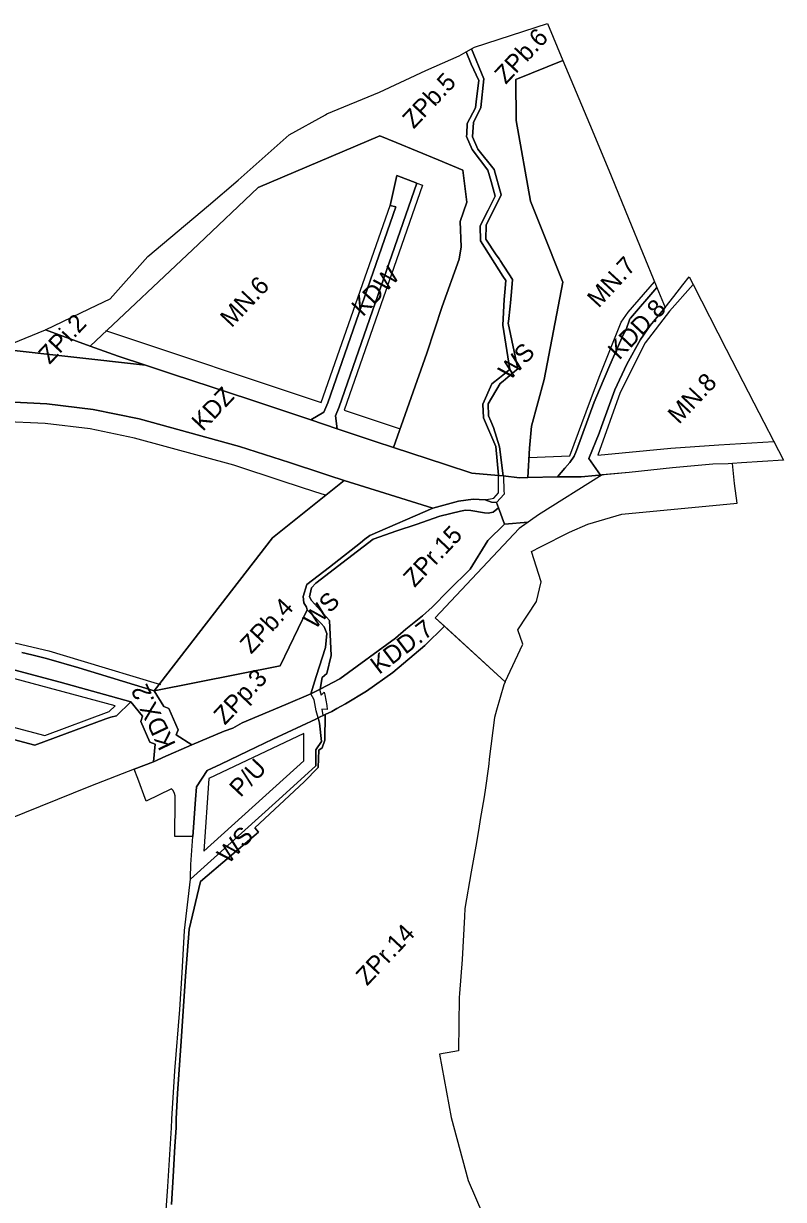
# Model space of a CAD drawing. Extents: x 7425782 to 7428854, y 5550411 to 5553074.
# Drawn here: x 7427672 to 7428056, y 5552172 to 5552767 of the extents above; entities that cross this region are included whole.
import ezdxf

# ---------------------------------------------------------------- set-up
doc = ezdxf.new("R2010")
doc.units = 0
for name, color, linetype in [('LIN_Linie rozgraniczajace WS', 7, 'Continuous'), ('LIN_linie_rozgraniczajace', 7, 'Continuous'), ('LIN_nieprzekraczalna linia zabudowy', 7, 'Continuous'), ('tereny MPZP_MISTRZEJOWICE PN', 7, 'Continuous'), ('TXT_oznaczenia przeznaczen', 7, 'Continuous')]:
    doc.layers.add(name, color=color, linetype=linetype)

msp = doc.modelspace()

# ---------------------------------------------------------------- linework, layer by layer
at = {"layer": 'LIN_Linie rozgraniczajace WS'}
for points in [[(7427906.08, 5552526.17), (7427905.67, 5552526.1), (7427910, 5552526.88), (7427912.32, 5552529.6), (7427912.33, 5552535.03), (7427912.28, 5552538.48)], [(7427914.73, 5552538.21), (7427914.82, 5552537.54), (7427915.06, 5552531.01), (7427915.15, 5552528.95), (7427911.35, 5552524.81)], [(7427821.22, 5552415.84), (7427820.92, 5552417.05), (7427820.21, 5552419.43), (7427819.29, 5552424.95), (7427817.61, 5552428.03)], [(7427822.25, 5552430.41), (7427822.12, 5552429.7), (7427822.72, 5552427.29), (7427824.33, 5552428.85), (7427824.64, 5552427.49), (7427825.55, 5552422.1), (7427825.84, 5552420.03), (7427823.16, 5552420.23), (7427823.66, 5552417)]]:
    msp.add_lwpolyline(points, dxfattribs=at)
at = {"layer": 'LIN_linie_rozgraniczajace'}
for points in [[(7427944.77, 5552748.25), (7427921.04, 5552738.69), (7427921.27, 5552717.87), (7427928.59, 5552677.19), (7427933.91, 5552663.7), (7427944.91, 5552636.14), (7427935.44, 5552586.91), (7427929.02, 5552563.42), (7427927.97, 5552552.2), (7427927.09, 5552537.4), (7427922.99, 5552537.31), (7427914.73, 5552538.21), (7427912.88, 5552552.91), (7427909.86, 5552562.77), (7427908.5, 5552565.95), (7427907.26, 5552568.62), (7427907.04, 5552574.63), (7427913.25, 5552584.87), (7427914.73, 5552586.1), (7427917.05, 5552588.08), (7427920.48, 5552590.95), (7427922.07, 5552592.29), (7427917.23, 5552615.47), (7427917.32, 5552616.25), (7427918.22, 5552624.08), (7427918.37, 5552625.68), (7427918.86, 5552631.3), (7427919.41, 5552637.52), (7427913.13, 5552647.2), (7427912.79, 5552647.73), (7427911.14, 5552649.92), (7427905.88, 5552657.85), (7427906.08, 5552664.96), (7427913.65, 5552680.24), (7427910.08, 5552693.1), (7427901.83, 5552703.44), (7427899.27, 5552709.58), (7427899.71, 5552716.95), (7427903.41, 5552724.54), (7427904.9, 5552738.91), (7427898.71, 5552754.16), (7427900.19, 5552755.02), (7427937.02, 5552766.93)], [(7427914.73, 5552538.21), (7427912.28, 5552538.48), (7427912.28, 5552538.67), (7427910.99, 5552553.07), (7427904.83, 5552567.55), (7427904.43, 5552574.52), (7427909.04, 5552584.8), (7427912.78, 5552587.81), (7427914.53, 5552589.18), (7427916.77, 5552591.01), (7427918.09, 5552592.04), (7427914.58, 5552614.34), (7427915.13, 5552627.34), (7427915.47, 5552631.16), (7427916, 5552636.95), (7427914.54, 5552639.14), (7427903.31, 5552657.05), (7427903.03, 5552664.62), (7427907.09, 5552672.58), (7427910.63, 5552679.62), (7427908.59, 5552686.98), (7427906.89, 5552692.8), (7427899.07, 5552703.21), (7427896.25, 5552709.73), (7427896.35, 5552711.13), (7427896.46, 5552716.31), (7427900.66, 5552724.29), (7427901.27, 5552728.9), (7427902.46, 5552738.14), (7427898.48, 5552746.32), (7427895.94, 5552752.56), (7427898.71, 5552754.16), (7427904.9, 5552738.91), (7427903.41, 5552724.54), (7427899.71, 5552716.95), (7427899.27, 5552709.58), (7427901.83, 5552703.44), (7427910.08, 5552693.1), (7427913.65, 5552680.24), (7427906.08, 5552664.96), (7427905.88, 5552657.85), (7427911.14, 5552649.92), (7427912.79, 5552647.73), (7427913.13, 5552647.2), (7427919.41, 5552637.52), (7427918.86, 5552631.3), (7427918.37, 5552625.68), (7427918.22, 5552624.08), (7427917.32, 5552616.25), (7427917.23, 5552615.47), (7427922.07, 5552592.29), (7427920.48, 5552590.95), (7427917.05, 5552588.08), (7427914.73, 5552586.1), (7427913.25, 5552584.87), (7427907.04, 5552574.63), (7427907.26, 5552568.62), (7427908.5, 5552565.95), (7427909.86, 5552562.77), (7427912.88, 5552552.91)], [(7427912.28, 5552538.48), (7427898.8, 5552539.53), (7427885.64, 5552543.9), (7427859.3, 5552552.58), (7427876.15, 5552600.28), (7427883.95, 5552623.89), (7427892.49, 5552647.77), (7427893.42, 5552654), (7427892.94, 5552666.85), (7427896.34, 5552676.67), (7427894.38, 5552692.8), (7427881.88, 5552697.96), (7427860.65, 5552706.7), (7427852.41, 5552710.1), (7427790.92, 5552684.04), (7427760.79, 5552655.36), (7427706.13, 5552603.86), (7427683.49, 5552612.03), (7427705.59, 5552622.65), (7427709.38, 5552624.47), (7427716.17, 5552627.73), (7427735.23, 5552649.12), (7427765.84, 5552674.97), (7427780.87, 5552687.69), (7427806.59, 5552710.73), (7427824.96, 5552720.83), (7427825.63, 5552721.22), (7427852.15, 5552732.2), (7427875.71, 5552743.13), (7427892.48, 5552750.56), (7427895.94, 5552752.56), (7427898.48, 5552746.32), (7427902.46, 5552738.14), (7427901.27, 5552728.9), (7427900.66, 5552724.29), (7427896.46, 5552716.31), (7427896.35, 5552711.13), (7427896.25, 5552709.73), (7427899.07, 5552703.21), (7427906.89, 5552692.8), (7427908.59, 5552686.98), (7427910.63, 5552679.62), (7427907.09, 5552672.58), (7427903.03, 5552664.62), (7427903.31, 5552657.05), (7427914.54, 5552639.14), (7427916, 5552636.95), (7427915.47, 5552631.16), (7427915.13, 5552627.34), (7427914.58, 5552614.34), (7427918.09, 5552592.04), (7427916.77, 5552591.01), (7427914.53, 5552589.18), (7427912.78, 5552587.81), (7427909.04, 5552584.8), (7427904.43, 5552574.52), (7427904.83, 5552567.55), (7427910.99, 5552553.07), (7427912.28, 5552538.67)], [(7427992.33, 5552633.5), (7427979.03, 5552617.99), (7427978.74, 5552617.63), (7427976.88, 5552612.22), (7427974.98, 5552608.9), (7427974.1, 5552606.87), (7427968.65, 5552594.28), (7427963.42, 5552581.94), (7427960.62, 5552575.43), (7427951.83, 5552551.06), (7427950.63, 5552548.11), (7427948.35, 5552544.99), (7427945.92, 5552542.07), (7427942.17, 5552537.73), (7427927.09, 5552537.4), (7427927.97, 5552552.2), (7427929.02, 5552563.42), (7427935.44, 5552586.91), (7427944.91, 5552636.14), (7427933.91, 5552663.7), (7427928.59, 5552677.19), (7427921.27, 5552717.87), (7427921.04, 5552738.69), (7427944.77, 5552748.25), (7427959.74, 5552713.08), (7427969.3, 5552689.87), (7427978.27, 5552667.94), (7427992.02, 5552634.27)], [(7427859.3, 5552552.58), (7427849.99, 5552555.65), (7427830.92, 5552562), (7427829.93, 5552568.55), (7427831.84, 5552573.21), (7427871.1, 5552686.24), (7427861.05, 5552690.03), (7427857.64, 5552674.95), (7427860.55, 5552674.2), (7427826.13, 5552575.24), (7427824.17, 5552570.36), (7427817.49, 5552566.48), (7427786.66, 5552576.76), (7427747.68, 5552589.71), (7427733.95, 5552594.24), (7427720.23, 5552598.77), (7427706.13, 5552603.86), (7427760.79, 5552655.36), (7427790.92, 5552684.04), (7427852.41, 5552710.1), (7427860.65, 5552706.7), (7427881.88, 5552697.96), (7427894.38, 5552692.8), (7427896.34, 5552676.67), (7427892.94, 5552666.85), (7427893.42, 5552654), (7427892.49, 5552647.77), (7427883.95, 5552623.89), (7427876.15, 5552600.28)], [(7427830.92, 5552562), (7427817.49, 5552566.48), (7427824.17, 5552570.36), (7427826.13, 5552575.24), (7427860.55, 5552674.2), (7427857.64, 5552674.95), (7427861.05, 5552690.03), (7427871.1, 5552686.24), (7427831.84, 5552573.21), (7427829.93, 5552568.55)], [(7428030.6, 5552544.5), (7428028.35, 5552544.37), (7428020.56, 5552544.13), (7428000.32, 5552542.25), (7427978.41, 5552539.99), (7427963.87, 5552538.61), (7427957.92, 5552546.98), (7427963.17, 5552559.82), (7427964.37, 5552563.11), (7427971.12, 5552581.68), (7427977.11, 5552594.63), (7427984, 5552607.11), (7427988.94, 5552614.28), (7427996.46, 5552623.42), (7428000.97, 5552628.91), (7428005.54, 5552634.82), (7428008.69, 5552638.88), (7428010.65, 5552635.02), (7428027.29, 5552602.24), (7428041.33, 5552575.22), (7428056.31, 5552546.16), (7428035.13, 5552544.77)], [(7427996.46, 5552623.42), (7427988.94, 5552614.28), (7427984, 5552607.11), (7427977.11, 5552594.63), (7427971.12, 5552581.68), (7427964.37, 5552563.11), (7427963.17, 5552559.82), (7427957.92, 5552546.98), (7427963.87, 5552538.61), (7427961.38, 5552538.38), (7427954.13, 5552537.73), (7427942.17, 5552537.73), (7427945.92, 5552542.07), (7427948.35, 5552544.99), (7427950.63, 5552548.11), (7427951.83, 5552551.06), (7427960.62, 5552575.43), (7427963.42, 5552581.94), (7427968.65, 5552594.28), (7427974.1, 5552606.87), (7427974.98, 5552608.9), (7427976.88, 5552612.22), (7427978.74, 5552617.63), (7427979.03, 5552617.99), (7427992.33, 5552633.5)], [(7427706.13, 5552603.86), (7427720.23, 5552598.77), (7427733.95, 5552594.24), (7427659.97, 5552602.41), (7427683.49, 5552612.03)], [(7427879.19, 5552521.86), (7427847.26, 5552508.01), (7427844.89, 5552506.17), (7427842.69, 5552504.43), (7427829.32, 5552493.91), (7427826.95, 5552492.09), (7427815.57, 5552483.29), (7427813.65, 5552477.16), (7427814.03, 5552474.02), (7427815.36, 5552471.77), (7427815.76, 5552470.45), (7427802, 5552442.19), (7427738.37, 5552429.54), (7427798.17, 5552506.95), (7427834.33, 5552535.97), (7427854.84, 5552529.5)], [(7427912.33, 5552522.14), (7427909.69, 5552519.87), (7427907.17, 5552519.37), (7427905.3, 5552519.55), (7427898.29, 5552520.7), (7427895.69, 5552520.84), (7427893.11, 5552520.4), (7427882.69, 5552517.81), (7427870.71, 5552513.72), (7427860.97, 5552510.4), (7427848.98, 5552506.31), (7427836.06, 5552496.31), (7427820.12, 5552483.94), (7427817.93, 5552481.66), (7427816.82, 5552477.15), (7427817.87, 5552475.29), (7427827.03, 5552465.14), (7427827.85, 5552447.36), (7427825.69, 5552438.3), (7427823.31, 5552436.24), (7427822.25, 5552430.41), (7427821.53, 5552430.05), (7427817.61, 5552428.03), (7427820.3, 5552436.76), (7427824.91, 5552451.48), (7427825.66, 5552458.58), (7427824.31, 5552461.84), (7427822.77, 5552463.58), (7427815.76, 5552470.45), (7427815.36, 5552471.77), (7427814.03, 5552474.02), (7427813.65, 5552477.16), (7427815.57, 5552483.29), (7427826.95, 5552492.09), (7427829.32, 5552493.91), (7427842.69, 5552504.43), (7427844.89, 5552506.17), (7427847.26, 5552508.01), (7427879.19, 5552521.86), (7427892.09, 5552525.51), (7427899.59, 5552526.51), (7427905.67, 5552526.1), (7427908.76, 5552524.93), (7427911.35, 5552524.81)], [(7427915.39, 5552513.8), (7427906.99, 5552505.63), (7427897.99, 5552491.09), (7427887.07, 5552480.21), (7427878.77, 5552471.93), (7427873.95, 5552467.51), (7427865.57, 5552460.79), (7427860.32, 5552456.23), (7427832.21, 5552435.54), (7427822.25, 5552430.41), (7427823.31, 5552436.24), (7427825.69, 5552438.3), (7427827.85, 5552447.36), (7427827.03, 5552465.14), (7427817.87, 5552475.29), (7427816.82, 5552477.15), (7427817.93, 5552481.66), (7427820.12, 5552483.94), (7427836.06, 5552496.31), (7427848.98, 5552506.31), (7427860.97, 5552510.4), (7427870.71, 5552513.72), (7427882.69, 5552517.81), (7427893.11, 5552520.4), (7427895.69, 5552520.84), (7427898.29, 5552520.7), (7427905.3, 5552519.55), (7427907.17, 5552519.37), (7427909.69, 5552519.87), (7427912.33, 5552522.14)], [(7427726.52, 5552423.94), (7427719.29, 5552416.96), (7427716.55, 5552416.25), (7427713.95, 5552415.33), (7427678.18, 5552402.12), (7427520.16, 5552444.01), (7427520.89, 5552457.43), (7427522.87, 5552473.59), (7427523.81, 5552478.43), (7427552.66, 5552470.74), (7427578.67, 5552463.71), (7427580.17, 5552463.41), (7427690.89, 5552433.92)], [(7427817.61, 5552428.03), (7427804.89, 5552422.63), (7427782.83, 5552413.32), (7427778.19, 5552410.75), (7427773.7, 5552409.23), (7427757.4, 5552402.21), (7427749.56, 5552407.25), (7427750.59, 5552409.88), (7427745.87, 5552420.6), (7427743.24, 5552421.63), (7427738.37, 5552429.54), (7427802, 5552442.19), (7427815.76, 5552470.45), (7427822.77, 5552463.58), (7427824.31, 5552461.84), (7427825.66, 5552458.58), (7427824.91, 5552451.48), (7427820.3, 5552436.76)], [(7427756.73, 5552334.36), (7427756.82, 5552335.16), (7427756.89, 5552341.83), (7427757.94, 5552355.83), (7427759.35, 5552374.64), (7427759.72, 5552381.09), (7427765.23, 5552389.29), (7427772.06, 5552392.56), (7427785.74, 5552399.04), (7427798.42, 5552405.04), (7427820.09, 5552415.31), (7427821.22, 5552415.84), (7427821.89, 5552413.15), (7427822.95, 5552404.01), (7427820.05, 5552399.72), (7427820.04, 5552391.55), (7427801.35, 5552374.67)]]:
    msp.add_lwpolyline(points, close=True, dxfattribs=at)
for points in [[(7427659.97, 5552602.41), (7427733.95, 5552594.24), (7427747.68, 5552589.71), (7427786.66, 5552576.76), (7427817.49, 5552566.48), (7427830.92, 5552562), (7427849.99, 5552555.65), (7427859.3, 5552552.58), (7427885.64, 5552543.9), (7427898.8, 5552539.53), (7427912.28, 5552538.48), (7427914.73, 5552538.21), (7427922.99, 5552537.31), (7427927.09, 5552537.4), (7427942.17, 5552537.73), (7427954.13, 5552537.73), (7427961.38, 5552538.38), (7427963.87, 5552538.61), (7427964.71, 5552538.69)], [(7427660.88, 5552575.75), (7427684.15, 5552574.7), (7427707.59, 5552571.82), (7427730.74, 5552567.1), (7427781.57, 5552553.16), (7427806.68, 5552544.92), (7427823.65, 5552539.35), (7427826.6, 5552538.42), (7427834.33, 5552535.97), (7427798.17, 5552506.95), (7427738.37, 5552429.54), (7427700.25, 5552441.12), (7427684.06, 5552445.88), (7427676.56, 5552447.74), (7427671.54, 5552448.86)], [(7427927.34, 5552514.81), (7427915.39, 5552513.8), (7427912.33, 5552522.14), (7427911.35, 5552524.81), (7427908.76, 5552524.93), (7427905.67, 5552526.1), (7427899.59, 5552526.51), (7427892.09, 5552525.51), (7427879.19, 5552521.86), (7427854.84, 5552529.5), (7427834.33, 5552535.97), (7427826.6, 5552538.42), (7427823.65, 5552539.35), (7427806.68, 5552544.92), (7427781.57, 5552553.16), (7427730.74, 5552567.1), (7427707.59, 5552571.82), (7427684.15, 5552574.7), (7427660.88, 5552575.75)], [(7427964.71, 5552538.69), (7427932.58, 5552518.52), (7427922.75, 5552511.57), (7427880.28, 5552466.5)], [(7427885.02, 5552462.18), (7427875.15, 5552452.44), (7427859.03, 5552438.87), (7427845.61, 5552429.36), (7427835.01, 5552422.91), (7427830.73, 5552420.55), (7427828.12, 5552419.11), (7427824.81, 5552417.54), (7427821.22, 5552415.84), (7427820.09, 5552415.31), (7427798.42, 5552405.04), (7427785.74, 5552399.04), (7427772.06, 5552392.56), (7427765.23, 5552389.29), (7427759.72, 5552381.09), (7427759.35, 5552374.64), (7427757.94, 5552355.83), (7427748.76, 5552355.93), (7427749.02, 5552374.22), (7427749.05, 5552376.48), (7427748.65, 5552377.72), (7427747.94, 5552379.17), (7427747.22, 5552379.93), (7427734.27, 5552373.72), (7427730.09, 5552385.27), (7427728.29, 5552389.92), (7427738.03, 5552393.73), (7427739.63, 5552394.36), (7427742.78, 5552395.92), (7427757.4, 5552402.21), (7427773.7, 5552409.23), (7427778.19, 5552410.75), (7427782.83, 5552413.32), (7427804.89, 5552422.63), (7427817.61, 5552428.03), (7427821.53, 5552430.05), (7427822.25, 5552430.41), (7427832.21, 5552435.54), (7427860.32, 5552456.23), (7427865.57, 5552460.79), (7427873.95, 5552467.51), (7427878.77, 5552471.93), (7427887.07, 5552480.21), (7427897.99, 5552491.09), (7427906.99, 5552505.63), (7427915.39, 5552513.8), (7427927.34, 5552514.81)], [(7427671.54, 5552448.86), (7427676.56, 5552447.74), (7427684.06, 5552445.88), (7427700.25, 5552441.12), (7427738.37, 5552429.54), (7427743.24, 5552421.63), (7427745.87, 5552420.6), (7427750.59, 5552409.88), (7427749.56, 5552407.25), (7427757.4, 5552402.21), (7427742.78, 5552395.92), (7427739.63, 5552394.36), (7427738.03, 5552393.73), (7427738.83, 5552402.53), (7427736.2, 5552403.56), (7427731.6, 5552414.01), (7427732.44, 5552416.72), (7427726.52, 5552423.94), (7427690.89, 5552433.92), (7427580.17, 5552463.41)], [(7427880.28, 5552466.5), (7427885.02, 5552462.18), (7427915.79, 5552434.07)], [(7427747.07, 5552169.79), (7427748.12, 5552186.94), (7427748.91, 5552199.37), (7427749.55, 5552208.64), (7427749.56, 5552213.16), (7427750.25, 5552225.97), (7427751.98, 5552252.35), (7427754.29, 5552285.24), (7427756, 5552309.05), (7427761.73, 5552333.16), (7427791.16, 5552358.12), (7427789.31, 5552360.31), (7427814.24, 5552383.54), (7427821.25, 5552390.77), (7427821.61, 5552399.48), (7427823.24, 5552400.75), (7427824.65, 5552404.64), (7427824.81, 5552417.54), (7427828.12, 5552419.11), (7427830.73, 5552420.55), (7427835.01, 5552422.91), (7427845.61, 5552429.36), (7427859.03, 5552438.87), (7427875.15, 5552452.44), (7427885.02, 5552462.18)], [(7427520.16, 5552444.01), (7427678.18, 5552402.12), (7427713.95, 5552415.33), (7427716.55, 5552416.25), (7427719.29, 5552416.96), (7427726.52, 5552423.94), (7427732.44, 5552416.72), (7427731.6, 5552414.01), (7427736.2, 5552403.56), (7427738.83, 5552402.53), (7427738.03, 5552393.73), (7427728.29, 5552389.92), (7427706.22, 5552381.27), (7427664.06, 5552364.35)], [(7427915.79, 5552434.07), (7427915.05, 5552432.59), (7427911.35, 5552419.78), (7427910.26, 5552416.03), (7427907.65, 5552394.98), (7427907.41, 5552392.57), (7427907.07, 5552390.14), (7427905.72, 5552380.58), (7427905.06, 5552375.96), (7427903.13, 5552364.45), (7427902.36, 5552359.87), (7427900.87, 5552351.01), (7427898.61, 5552338.06), (7427895.38, 5552319.45), (7427895.15, 5552315.39), (7427893.96, 5552293.68), (7427892.63, 5552276.6), (7427892.47, 5552274.5), (7427892.09, 5552247.47), (7427889.29, 5552246.99), (7427882.62, 5552245.84), (7427888.5, 5552213.87), (7427896.99, 5552181.92), (7427904.38, 5552164.78)], [(7427743.79, 5552157.59), (7427745.25, 5552178.93), (7427747.08, 5552208.68), (7427747.35, 5552213.06), (7427748.84, 5552237.46), (7427751.27, 5552268.51), (7427752.52, 5552287.01), (7427753.77, 5552308.45), (7427756.73, 5552334.36), (7427801.35, 5552374.67), (7427820.04, 5552391.55), (7427820.05, 5552399.72), (7427822.95, 5552404.01), (7427821.89, 5552413.15), (7427821.22, 5552415.84), (7427824.81, 5552417.54), (7427824.65, 5552404.64), (7427823.24, 5552400.75), (7427821.61, 5552399.48), (7427821.25, 5552390.77), (7427814.24, 5552383.54), (7427789.31, 5552360.31), (7427791.16, 5552358.12), (7427761.73, 5552333.16), (7427756, 5552309.05), (7427754.29, 5552285.24), (7427751.98, 5552252.35), (7427750.25, 5552225.97), (7427749.56, 5552213.16), (7427749.55, 5552208.64), (7427748.91, 5552199.37), (7427748.12, 5552186.94), (7427747.07, 5552169.79)]]:
    msp.add_lwpolyline(points, dxfattribs=at)
at = {"layer": 'LIN_nieprzekraczalna linia zabudowy'}
for p, q in [((7427927.69, 5552547.44), (7427948.37, 5552548.37)), ((7427718.72, 5552421.94), (7427534.94, 5552471.33))]:
    msp.add_line(p, q, dxfattribs=at)
for points in [[(7427822.77, 5552575.3), (7427857.64, 5552674.95), (7427861.04, 5552689.65)], [(7427871.1, 5552686.24), (7427873.91, 5552685.18), (7427834.39, 5552571.41)], [(7427948.37, 5552548.37), (7427958.83, 5552576.48), (7427963.52, 5552588.95), (7427970.92, 5552607.5), (7427974.26, 5552615.87), (7427977.78, 5552621), (7427991.18, 5552636.32)], [(7428010.65, 5552635.02), (7427998.78, 5552621.51), (7427986.47, 5552605.41), (7427973.84, 5552580.42), (7427962.56, 5552548.76)], [(7427713.78, 5552611.76), (7427822.77, 5552575.3)], [(7427834.39, 5552571.41), (7427862.61, 5552561.94)], [(7427824.92, 5552528.41), (7427819.51, 5552530.1), (7427803.54, 5552535.43), (7427778.69, 5552543.59), (7427728.41, 5552557.37), (7427705.98, 5552561.94), (7427683.31, 5552564.73), (7427660.84, 5552565.74), (7427643.09, 5552565.09), (7427631.17, 5552564.23), (7427615.03, 5552562.37), (7427590.46, 5552557.51), (7427570.44, 5552551.89), (7427508.37, 5552532.06), (7427499.23, 5552502.04)], [(7427962.56, 5552548.76), (7427999.35, 5552552.21), (7428023.62, 5552553.9), (7428051.45, 5552555.61)], [(7427534.94, 5552471.33), (7427529.32, 5552447.81), (7427683.09, 5552406.89), (7427715.66, 5552419.02), (7427718.72, 5552421.94)], [(7427662.97, 5552455.02), (7427685.09, 5552449.75), (7427701.4, 5552444.95), (7427741.62, 5552432.74)], [(7427814.07, 5552407.97), (7427766.03, 5552385.23), (7427763.44, 5552348.51), (7427814.05, 5552394.22), (7427814.07, 5552407.97)]]:
    msp.add_lwpolyline(points, dxfattribs=at)
at = {"layer": 'tereny MPZP_MISTRZEJOWICE PN'}
for p, q in [((7428030.6, 5552544.5), (7428028.35, 5552544.37)), ((7428031.58, 5552534.39), (7428030.6, 5552544.5)), ((7427931.62, 5552474.67), (7427933.86, 5552484.66)), ((7427915.79, 5552434.07), (7427924.66, 5552453.1))]:
    msp.add_line(p, q, dxfattribs=at)
for points in [[(7428028.35, 5552544.37), (7428020.56, 5552544.13), (7428000.32, 5552542.25), (7427978.41, 5552539.99), (7427964.69, 5552538.68), (7427932.58, 5552518.52), (7427922.75, 5552511.57), (7427880.28, 5552466.5), (7427915.79, 5552434.07)], [(7427957.5, 5552513.78), (7427974.62, 5552518.83), (7428032.95, 5552524.46), (7428031.58, 5552534.39)], [(7427933.86, 5552484.66), (7427929, 5552500.03), (7427933.5, 5552502.31), (7427948.28, 5552509.83), (7427957.5, 5552513.78)], [(7427924.66, 5552453.1), (7427922.18, 5552460.32), (7427931.62, 5552474.67)]]:
    msp.add_lwpolyline(points, dxfattribs=at)

# ---------------------------------------------------------------- texts
at = {"layer": 'TXT_oznaczenia przeznaczen'}
for s, rotation, p in [('ZPb.6', 46.77361, (7427916.03, 5552735.86)), ('ZPb.5', 46.77361, (7427869.51, 5552713.33)), ('MN.7', 47.34541, (7427962.92, 5552622.71)), ('KDW', 46.77361, (7427843.8, 5552618.37)), ('MN.6', 46.77361, (7427777.45, 5552612.82)), ('KDD.8', 46.77361, (7427973.32, 5552596.46)), ('ZPi.2', 46.77361, (7427685.56, 5552594.26)), ('WS', 46.77361, (7427918.04, 5552586.03)), ('MN.8', 46.77361, (7428003.53, 5552563.95)), ('KDZ', 46.77361, (7427762.98, 5552560.35)), ('ZPr.15', 46.77361, (7427869.95, 5552481.45)), ('ZPb.4', 46.77361, (7427787.39, 5552447.75)), ('WS', 46.77361, (7427819.48, 5552460.17)), ('KDD.7', 37.23798, (7427852.01, 5552437.56)), ('ZPp.3', 46.77361, (7427774.12, 5552411.92)), ('KDX.2', 115.4967, (7427749.48, 5552402.46)), ('P/U', 46.77361, (7427782.03, 5552375.29)), ('WS', 47.34541, (7427775.92, 5552341.56)), ('ZPr.14', 46.77361, (7427845.96, 5552280.06))]:
    msp.add_text(s, height=9, rotation=rotation, dxfattribs=at).set_placement(p)

doc.saveas('drawing.dxf')
